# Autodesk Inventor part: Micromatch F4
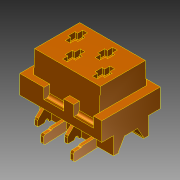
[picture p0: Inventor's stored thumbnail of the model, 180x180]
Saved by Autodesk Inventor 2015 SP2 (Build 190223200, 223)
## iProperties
Created: 2015-08
Part Number: Micromatch F4
Material: Allgemein
Document SubType Name: Modeling
Designer: rYan
Density: 1 g/cm^3
Appearance: Vorgabe
Author: workeradm
Title: c-188275-4-u-3d.igs
Organization: Unknown
Description: PTC IGES file: c-188275-4-u-3d.igs
Sending System: Pro/ENGINEER by Parametric Technology Corporation
Preprocessor: 2010430
Minimum Resolution: 0.001115
Sending System Product ID: C-188275-4
Receiving System Product ID: C-188275-4
Sent Units: Millimeter
Translation Standard: USPRO/IPO100 IGES 5.2
Author: rYan
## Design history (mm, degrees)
node "c-188275-4-u-3d1"
feature "Zusammengesetzt1"
node "Fläche1"
